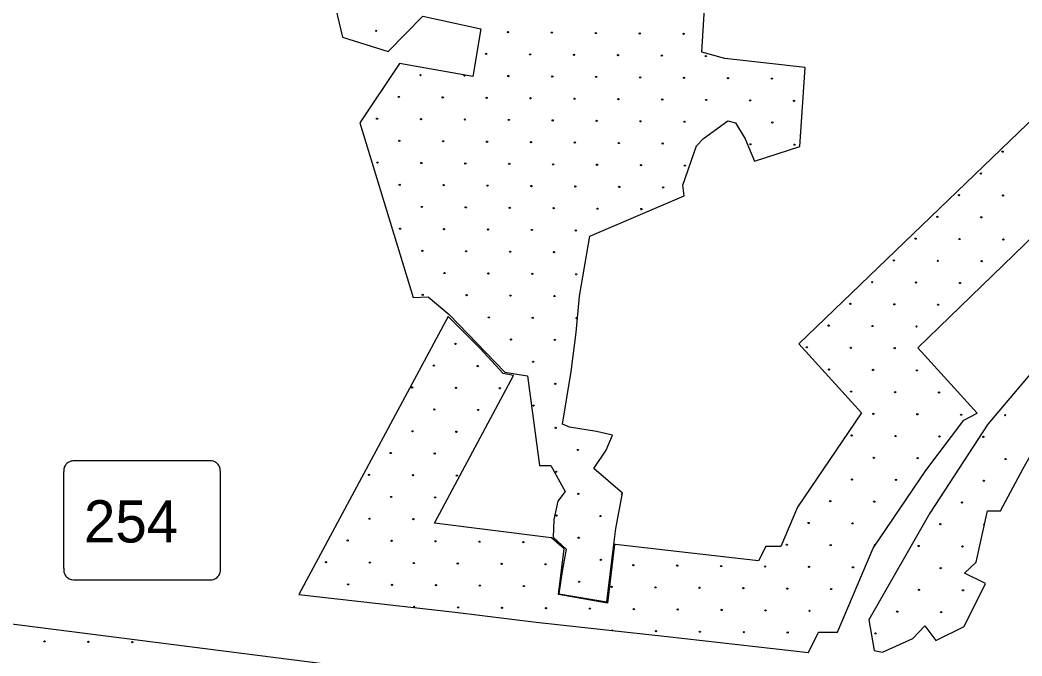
# Model space of a CAD drawing. Extents: x 1612280 to 1883141, y 560852 to 780851.
# Drawn here: x 1728435 to 1737209, y 621659 to 627229 of the extents above; entities that cross this region are included whole.
import ezdxf

# ---------------------------------------------------------------- set-up
doc = ezdxf.new("R2010")
doc.units = 0
for name, color, linetype in [('DESIGN - EROSION CONTROL - Devices', 7, 'Continuous'), ('DESIGN - ROW - Slope Lines', 7, 'Continuous'), ('DESIGN - SCRATCH - User 1', 7, 'Continuous')]:
    doc.layers.add(name, color=color, linetype=linetype)

msp = doc.modelspace()

# ---------------------------------------------------------------- linework, layer by layer
at = {"layer": 'DESIGN - EROSION CONTROL - Devices'}
for centre in [(1731554.3, 627133.4), (1731554.3, 627133.4), (1732707.9, 627122.2), (1732707.9, 627122.2), (1733092.5, 627118.5), (1733092.5, 627118.5), (1733477, 627114.8), (1733477, 627114.8), (1733861.6, 627111), (1733861.6, 627111), (1734246.1, 627107.3), (1734246.1, 627107.3), (1732517.5, 626931.8), (1732517.5, 626931.8), (1732902.1, 626928.1), (1732902.1, 626928.1), (1733286.6, 626924.4), (1733286.6, 626924.4), (1733671.2, 626920.6), (1733671.2, 626920.6), (1734055.7, 626916.9), (1734055.7, 626916.9), (1734440.3, 626913.2), (1734440.3, 626913.2), (1731942.6, 626745.1), (1731942.6, 626745.1), (1732327.1, 626741.4), (1732327.1, 626741.4), (1732711.7, 626737.7), (1732711.7, 626737.7), (1733096.2, 626733.9), (1733096.2, 626733.9), (1733480.8, 626730.2), (1733480.8, 626730.2), (1733865.3, 626726.5), (1733865.3, 626726.5), (1734249.9, 626722.7), (1734249.9, 626722.7), (1734634.4, 626719), (1734634.4, 626719), (1735019, 626715.3), (1735019, 626715.3), (1731752.1, 626554.7), (1731752.1, 626554.7), (1732136.7, 626551), (1732136.7, 626551), (1732521.2, 626547.3), (1732521.2, 626547.3), (1732905.8, 626543.5), (1732905.8, 626543.5), (1733290.4, 626539.8), (1733290.4, 626539.8), (1733674.9, 626536.1), (1733674.9, 626536.1), (1734059.5, 626532.3), (1734059.5, 626532.3), (1734444, 626528.6), (1734444, 626528.6), (1734828.6, 626524.9), (1734828.6, 626524.9), (1735213.1, 626521.1), (1735213.1, 626521.1), (1731561.7, 626364.3), (1731561.7, 626364.3), (1731946.3, 626360.6), (1731946.3, 626360.6), (1732330.8, 626356.9), (1732330.8, 626356.9), (1732715.4, 626353.1), (1732715.4, 626353.1), (1733099.9, 626349.4), (1733099.9, 626349.4), (1733484.5, 626345.7), (1733484.5, 626345.7), (1733869, 626341.9), (1733869, 626341.9), (1734253.6, 626338.2), (1734253.6, 626338.2), (1735022.7, 626330.7), (1735022.7, 626330.7), (1731755.9, 626170.2), (1731755.9, 626170.2), (1732140.4, 626166.4), (1732140.4, 626166.4), (1732525, 626162.7), (1732525, 626162.7), (1732909.5, 626159), (1732909.5, 626159), (1733294.1, 626155.2), (1733294.1, 626155.2), (1733678.6, 626151.5), (1733678.6, 626151.5), (1734063.2, 626147.8), (1734063.2, 626147.8), (1734832.3, 626140.3), (1734832.3, 626140.3), (1735216.9, 626136.6), (1735216.9, 626136.6), (1737039.2, 626075.8), (1737039.2, 626075.8), (1731565.5, 625979.8), (1731565.5, 625979.8), (1731950, 625976), (1731950, 625976), (1732334.6, 625972.3), (1732334.6, 625972.3), (1732719.1, 625968.6), (1732719.1, 625968.6), (1733103.7, 625964.8), (1733103.7, 625964.8), (1733488.2, 625961.1), (1733488.2, 625961.1), (1733872.8, 625957.4), (1733872.8, 625957.4), (1734257.3, 625953.6), (1734257.3, 625953.6), (1736848.7, 625885.4), (1736848.7, 625885.4), (1731759.6, 625785.6), (1731759.6, 625785.6), (1732144.2, 625781.9), (1732144.2, 625781.9), (1732528.7, 625778.2), (1732528.7, 625778.2), (1732913.3, 625774.4), (1732913.3, 625774.4), (1733297.8, 625770.7), (1733297.8, 625770.7), (1733682.4, 625767), (1733682.4, 625767), (1734066.9, 625763.2), (1734066.9, 625763.2), (1736658.3, 625695), (1736658.3, 625695), (1737042.9, 625691.2), (1737042.9, 625691.2), (1731953.8, 625591.5), (1731953.8, 625591.5), (1732338.3, 625587.8), (1732338.3, 625587.8), (1732722.9, 625584), (1732722.9, 625584), (1733107.4, 625580.3), (1733107.4, 625580.3), (1733492, 625576.5), (1733492, 625576.5), (1733876.5, 625572.8), (1733876.5, 625572.8), (1736467.9, 625504.5), (1736467.9, 625504.5), (1736852.5, 625500.8), (1736852.5, 625500.8), (1731763.3, 625401.1), (1731763.3, 625401.1), (1732147.9, 625397.3), (1732147.9, 625397.3), (1732532.4, 625393.6), (1732532.4, 625393.6), (1732917, 625389.9), (1732917, 625389.9), (1733301.6, 625386.1), (1733301.6, 625386.1), (1736277.5, 625314.1), (1736277.5, 625314.1), (1736662.1, 625310.4), (1736662.1, 625310.4), (1737046.6, 625306.7), (1737046.6, 625306.7), (1731957.5, 625206.9), (1731957.5, 625206.9), (1732342, 625203.2), (1732342, 625203.2), (1732726.6, 625199.5), (1732726.6, 625199.5), (1733111.1, 625195.7), (1733111.1, 625195.7), (1736087.1, 625123.7), (1736087.1, 625123.7), (1736471.7, 625120), (1736471.7, 625120), (1736856.2, 625116.3), (1736856.2, 625116.3), (1732151.6, 625012.8), (1732151.6, 625012.8), (1732536.2, 625009.1), (1732536.2, 625009.1), (1732920.7, 625005.3), (1732920.7, 625005.3), (1733305.3, 625001.6), (1733305.3, 625001.6), (1735896.7, 624933.3), (1735896.7, 624933.3), (1736281.2, 624929.6), (1736281.2, 624929.6), (1736665.8, 624925.9), (1736665.8, 624925.9), (1731961.2, 624822.4), (1731961.2, 624822.4), (1732345.8, 624818.6), (1732345.8, 624818.6), (1732730.3, 624814.9), (1732730.3, 624814.9), (1733114.9, 624811.2), (1733114.9, 624811.2), (1735706.3, 624742.9), (1735706.3, 624742.9), (1736090.8, 624739.2), (1736090.8, 624739.2), (1736475.4, 624735.4), (1736475.4, 624735.4), (1732539.9, 624624.5), (1732539.9, 624624.5), (1732924.5, 624620.8), (1732924.5, 624620.8), (1733309, 624617), (1733309, 624617), (1735515.9, 624552.5), (1735515.9, 624552.5), (1735900.4, 624548.8), (1735900.4, 624548.8), (1736285, 624545), (1736285, 624545), (1732734.1, 624430.4), (1732734.1, 624430.4), (1733118.6, 624426.6), (1733118.6, 624426.6), (1732249, 624392), (1732249, 624392), (1735325.5, 624362.1), (1735325.5, 624362.1), (1735710, 624358.4), (1735710, 624358.4), (1736094.6, 624354.6), (1736094.6, 624354.6), (1732058.6, 624201.5), (1732058.6, 624201.5), (1732443.2, 624197.8), (1732443.2, 624197.8), (1732928.2, 624236.2), (1732928.2, 624236.2), (1735519.6, 624167.9), (1735519.6, 624167.9), (1735904.2, 624164.2), (1735904.2, 624164.2), (1736288.7, 624160.5), (1736288.7, 624160.5), (1731868.2, 624011.1), (1731868.2, 624011.1), (1732252.8, 624007.4), (1732252.8, 624007.4), (1732637.3, 624003.7), (1732637.3, 624003.7), (1733122.3, 624042.1), (1733122.3, 624042.1), (1735713.8, 623973.8), (1735713.8, 623973.8), (1736098.3, 623970.1), (1736098.3, 623970.1), (1736482.9, 623966.3), (1736482.9, 623966.3), (1732062.4, 623817), (1732062.4, 623817), (1732446.9, 623813.3), (1732446.9, 623813.3), (1732931.9, 623851.7), (1732931.9, 623851.7), (1735907.9, 623779.7), (1735907.9, 623779.7), (1736292.4, 623775.9), (1736292.4, 623775.9), (1736677, 623772.2), (1736677, 623772.2), (1737061.6, 623768.5), (1737061.6, 623768.5), (1733126.1, 623657.5), (1733126.1, 623657.5), (1731872, 623626.6), (1731872, 623626.6), (1732256.5, 623622.9), (1732256.5, 623622.9), (1735717.5, 623589.3), (1735717.5, 623589.3), (1736102, 623585.5), (1736102, 623585.5), (1736486.6, 623581.8), (1736486.6, 623581.8), (1736871.1, 623578.1), (1736871.1, 623578.1), (1733320.2, 623463.4), (1733320.2, 623463.4), (1731681.5, 623436.2), (1731681.5, 623436.2), (1732066.1, 623432.4), (1732066.1, 623432.4), (1735911.6, 623395.1), (1735911.6, 623395.1), (1736296.2, 623391.4), (1736296.2, 623391.4), (1737065.3, 623383.9), (1737065.3, 623383.9), (1731491.1, 623245.8), (1731491.1, 623245.8), (1731875.7, 623242), (1731875.7, 623242), (1732260.2, 623238.3), (1732260.2, 623238.3), (1733129.8, 623273), (1733129.8, 623273), (1735721.2, 623204.7), (1735721.2, 623204.7), (1736105.8, 623201), (1736105.8, 623201), (1736874.9, 623193.5), (1736874.9, 623193.5), (1731685.3, 623051.6), (1731685.3, 623051.6), (1732069.8, 623047.9), (1732069.8, 623047.9), (1733324, 623078.8), (1733324, 623078.8), (1735530.8, 623014.3), (1735530.8, 623014.3), (1735915.4, 623010.6), (1735915.4, 623010.6), (1736684.5, 623003.1), (1736684.5, 623003.1), (1731494.9, 622861.2), (1731494.9, 622861.2), (1731879.4, 622857.5), (1731879.4, 622857.5), (1733133.5, 622888.4), (1733133.5, 622888.4), (1733518.1, 622884.7), (1733518.1, 622884.7), (1735340.4, 622823.9), (1735340.4, 622823.9), (1735725, 622820.1), (1735725, 622820.1), (1736494.1, 622812.7), (1736494.1, 622812.7), (1731304.5, 622670.8), (1731304.5, 622670.8), (1731689, 622667.1), (1731689, 622667.1), (1733327.7, 622694.3), (1733327.7, 622694.3), (1732073.6, 622663.3), (1732073.6, 622663.3), (1732458.1, 622659.6), (1732458.1, 622659.6), (1732842.7, 622655.9), (1732842.7, 622655.9), (1735150, 622633.5), (1735150, 622633.5), (1735534.5, 622629.7), (1735534.5, 622629.7), (1736303.6, 622622.3), (1736303.6, 622622.3), (1736688.2, 622618.5), (1736688.2, 622618.5), (1733521.8, 622500.1), (1733521.8, 622500.1), (1731114.1, 622480.4), (1731114.1, 622480.4), (1731498.6, 622476.7), (1731498.6, 622476.7), (1731883.2, 622472.9), (1731883.2, 622472.9), (1732267.7, 622469.2), (1732267.7, 622469.2), (1732652.3, 622465.5), (1732652.3, 622465.5), (1733036.8, 622461.7), (1733036.8, 622461.7), (1733805.9, 622454.3), (1733805.9, 622454.3), (1734190.5, 622450.5), (1734190.5, 622450.5), (1734575, 622446.8), (1734575, 622446.8), (1734959.6, 622443.1), (1734959.6, 622443.1), (1735344.1, 622439.3), (1735344.1, 622439.3), (1735728.7, 622435.6), (1735728.7, 622435.6), (1736497.8, 622428.1), (1736497.8, 622428.1), (1731308.2, 622286.3), (1731308.2, 622286.3), (1731692.7, 622282.5), (1731692.7, 622282.5), (1732077.3, 622278.8), (1732077.3, 622278.8), (1732461.9, 622275.1), (1732461.9, 622275.1), (1732846.4, 622271.3), (1732846.4, 622271.3), (1733331.4, 622309.7), (1733331.4, 622309.7), (1733615.5, 622263.9), (1733615.5, 622263.9), (1734000.1, 622260.1), (1734000.1, 622260.1), (1734384.6, 622256.4), (1734384.6, 622256.4), (1734769.2, 622252.6), (1734769.2, 622252.6), (1735153.7, 622248.9), (1735153.7, 622248.9), (1735538.3, 622245.2), (1735538.3, 622245.2), (1736307.4, 622237.7), (1736307.4, 622237.7), (1736691.9, 622234), (1736691.9, 622234), (1732271.4, 622084.6), (1732271.4, 622084.6), (1732656, 622080.9), (1732656, 622080.9), (1733040.5, 622077.2), (1733040.5, 622077.2), (1733425.1, 622073.4), (1733425.1, 622073.4), (1733809.7, 622069.7), (1733809.7, 622069.7), (1734194.2, 622066), (1734194.2, 622066), (1734578.8, 622062.2), (1734578.8, 622062.2), (1734963.3, 622058.5), (1734963.3, 622058.5), (1735347.9, 622054.8), (1735347.9, 622054.8), (1736117, 622047.3), (1736117, 622047.3), (1736501.5, 622043.6), (1736501.5, 622043.6), (1734003.8, 621875.6), (1734003.8, 621875.6), (1728648.9, 621787.1), (1728648.9, 621787.1), (1734388.4, 621871.8), (1734388.4, 621871.8), (1734772.9, 621868.1), (1734772.9, 621868.1), (1735157.5, 621864.4), (1735157.5, 621864.4), (1735926.6, 621856.9), (1735926.6, 621856.9), (1729033.4, 621783.4), (1729033.4, 621783.4), (1729418, 621779.7), (1729418, 621779.7)]:
    msp.add_circle(centre, 5.28, dxfattribs=at)
for centre, start, end in [((1733708.5, 623075.1), 75.50073, 263.45626), ((1736878.6, 622808.9), 58.23746, 276.59138), ((1735919.1, 622626), 32.37169, 259.39047), ((1730923.6, 622290), 287.00107, 16.61261), ((1731886.9, 622088.4), 271.24521, 255.91452), ((1733619.2, 621879.3), 40.66872, 126.38298)]:
    msp.add_arc(centre, 5.28, start, end, dxfattribs=at)
at = {"layer": 'DESIGN - ROW - Slope Lines'}
msp.add_line((1728817.1, 623266.8), (1728817.1, 622435), dxfattribs=at)
msp.add_line((1728817.1, 623266.8), (1728817.1, 622435), dxfattribs=at)
for points in [[(1730190, 623256.3), (1730189.9, 623264.1), (1730189.7, 623272.2), (1730188.7, 623286.8), (1730187.3, 623297.2), (1730185.5, 623308), (1730183.5, 623314), (1730180.3, 623320.6), (1730175.9, 623328.1), (1730170.5, 623335.5), (1730165.8, 623340.9), (1730159.9, 623346.5), (1730155.2, 623350.3), (1730148.8, 623354.8), (1730143.8, 623357.8), (1730135.5, 623361.8), (1730129.3, 623363.9), (1730122.2, 623365.3), (1730112.9, 623366.7), (1730104.8, 623367.5), (1730096.1, 623368.1), (1730083.8, 623368.2), (1730074.3, 623367.5), (1728917.1, 623368.2), (1728907.7, 623368.2), (1728897.4, 623367.5), (1728888.3, 623366.4), (1728879.2, 623364.7), (1728874.9, 623363.4), (1728867.7, 623360.3), (1728861.2, 623356.9), (1728856, 623353.7), (1728847.1, 623346.9), (1728841, 623341.1), (1728835.9, 623335.2), (1728831.9, 623329.9), (1728826.2, 623320.3), (1728822.8, 623312.9), (1728820.9, 623307.8), (1728820.2, 623304), (1728819.7, 623300.7), (1728818.8, 623293.4), (1728817.7, 623284.1), (1728817.3, 623276.2), (1728817.2, 623269.5), (1728817.1, 623251.6)], [(1730190, 623256.3), (1730189.9, 623264.1), (1730189.7, 623272.2), (1730188.7, 623286.8), (1730187.3, 623297.2), (1730185.5, 623308), (1730183.5, 623314), (1730180.3, 623320.6), (1730175.9, 623328.1), (1730170.5, 623335.5), (1730165.8, 623340.9), (1730159.9, 623346.5), (1730155.2, 623350.3), (1730148.8, 623354.8), (1730143.8, 623357.8), (1730135.5, 623361.8), (1730129.3, 623363.9), (1730122.2, 623365.3), (1730112.9, 623366.7), (1730104.8, 623367.5), (1730096.1, 623368.1), (1730083.8, 623368.2), (1730074.3, 623367.5), (1728917.1, 623368.2), (1728907.7, 623368.2), (1728897.4, 623367.5), (1728888.3, 623366.4), (1728879.2, 623364.7), (1728874.9, 623363.4), (1728867.7, 623360.3), (1728861.2, 623356.9), (1728856, 623353.7), (1728847.1, 623346.9), (1728841, 623341.1), (1728835.9, 623335.2), (1728831.9, 623329.9), (1728826.2, 623320.3), (1728822.8, 623312.9), (1728820.9, 623307.8), (1728820.2, 623304), (1728819.7, 623300.7), (1728818.8, 623293.4), (1728817.7, 623284.1), (1728817.3, 623276.2), (1728817.2, 623269.5), (1728817.1, 623251.6)], [(1730080.1, 622325.7), (1730100.8, 622326), (1730117.8, 622326.2), (1730128, 622328.7), (1730140.3, 622333.5), (1730151.5, 622339.9), (1730160.4, 622346.8), (1730168.5, 622354.8), (1730174.7, 622362.7), (1730180.7, 622372.5), (1730184.3, 622380.2), (1730186.9, 622387.3), (1730188.5, 622394.8), (1730189.2, 622403.1), (1730189.6, 622413.1), (1730190, 622436.4), (1730190, 623256.3)], [(1730080.1, 622325.7), (1730100.8, 622326), (1730117.8, 622326.2), (1730128, 622328.7), (1730140.3, 622333.5), (1730151.5, 622339.9), (1730160.4, 622346.8), (1730168.5, 622354.8), (1730174.7, 622362.7), (1730180.7, 622372.5), (1730184.3, 622380.2), (1730186.9, 622387.3), (1730188.5, 622394.8), (1730189.2, 622403.1), (1730189.6, 622413.1), (1730190, 622436.4), (1730190, 623256.3)], [(1728817.1, 622435), (1728817.3, 622426), (1728817.8, 622415.9), (1728818.6, 622406.4), (1728819.7, 622397.2), (1728821.1, 622388), (1728823.9, 622380.3), (1728827.3, 622373.1), (1728831.8, 622365.6), (1728837.2, 622358.3), (1728842.8, 622352.1), (1728850, 622345.5), (1728857, 622340.3), (1728865, 622335.6), (1728873.6, 622331.6), (1728882.5, 622328.5), (1728889.8, 622327.6), (1728904.7, 622326.4), (1728923.5, 622325.7), (1730080.1, 622325.7)], [(1728817.1, 622435), (1728817.3, 622426), (1728817.8, 622415.9), (1728818.6, 622406.4), (1728819.7, 622397.2), (1728821.1, 622388), (1728823.9, 622380.3), (1728827.3, 622373.1), (1728831.8, 622365.6), (1728837.2, 622358.3), (1728842.8, 622352.1), (1728850, 622345.5), (1728857, 622340.3), (1728865, 622335.6), (1728873.6, 622331.6), (1728882.5, 622328.5), (1728889.8, 622327.6), (1728904.7, 622326.4), (1728923.5, 622325.7), (1730080.1, 622325.7)]]:
    msp.add_lwpolyline(points, dxfattribs=at)
at = {"layer": 'DESIGN - SCRATCH - User 1'}
for points in [[(1731087.9, 627805.3), (1731258.1, 627080), (1731659, 626953.7), (1731961, 627261.4), (1732471.7, 627151.5), (1732400.3, 626733.9), (1731757.8, 626849.3)], [(1731087.9, 627805.3), (1731258.1, 627080), (1731659, 626953.7), (1731961, 627261.4), (1732471.7, 627151.5), (1732400.3, 626733.9), (1731757.8, 626849.3)], [(1734406, 626948.1), (1734436.8, 627476.1), (1734487.4, 627715.9)], [(1734406, 626948.1), (1734436.8, 627476.1), (1734487.4, 627715.9)], [(1737021.6, 622928.8), (1737218.5, 623299.9), (1737499.4, 623796.7), (1737882.4, 624199.2), (1738236.5, 624499.7), (1738713.8, 624934.9), (1738971.7, 625181.4), (1739106.4, 625458.7), (1739191.1, 625782.2), (1739241.2, 626132.7), (1739268.1, 626648.9), (1739325.1, 627161)], [(1737021.6, 622928.8), (1737218.5, 623299.9), (1737499.4, 623796.7), (1737882.4, 624199.2), (1738236.5, 624499.7), (1738713.8, 624934.9), (1738971.7, 625181.4), (1739106.4, 625458.7), (1739191.1, 625782.2), (1739241.2, 626132.7), (1739268.1, 626648.9), (1739325.1, 627161)], [(1738254.2, 626975), (1737949.5, 626985.3), (1735255.6, 624393.5), (1735803.4, 623788.5)], [(1738254.2, 626975), (1737949.5, 626985.3), (1735255.6, 624393.5), (1735803.4, 623788.5)], [(1735311.7, 626811.7), (1734608.3, 626890.9), (1734406, 626948.1)], [(1735311.7, 626811.7), (1734608.3, 626890.9), (1734406, 626948.1)], [(1731757.8, 626849.3), (1731411.9, 626327.3)], [(1731757.8, 626849.3), (1731411.9, 626327.3)], [(1735263.4, 626121), (1735311.7, 626811.7)], [(1735263.4, 626121), (1735311.7, 626811.7)], [(1731411.9, 626327.3), (1731878.6, 624799.7), (1732010.4, 624805.2), (1732193, 624650)], [(1731411.9, 626327.3), (1731878.6, 624799.7), (1732010.4, 624805.2), (1732193, 624650)], [(1734252.1, 625689.9), (1734238.9, 625782.2), (1734357.7, 626125.4), (1734419.2, 626191.4), (1734634.7, 626345.4)], [(1734252.1, 625689.9), (1734238.9, 625782.2), (1734357.7, 626125.4), (1734419.2, 626191.4), (1734634.7, 626345.4)], [(1734634.7, 626345.4), (1734700.6, 626327.8), (1734784.1, 626187), (1734867.7, 625993.4)], [(1734634.7, 626345.4), (1734700.6, 626327.8), (1734784.1, 626187), (1734867.7, 625993.4)], [(1734867.7, 625993.4), (1735263.4, 626121)], [(1734867.7, 625993.4), (1735263.4, 626121)], [(1736818.1, 623785.2), (1736298.5, 624359.1), (1738169.2, 626169.3), (1738230.8, 626123.1), (1738723.4, 625660.9), (1738477.1, 625268.1), (1737818.9, 624690.3)], [(1736818.1, 623785.2), (1736298.5, 624359.1), (1738169.2, 626169.3), (1738230.8, 626123.1), (1738723.4, 625660.9), (1738477.1, 625268.1), (1737818.9, 624690.3)], [(1733423.7, 625335.3), (1734252.1, 625689.9)], [(1733423.7, 625335.3), (1734252.1, 625689.9)], [(1733246.3, 623661.6), (1733186, 623689), (1733260, 624149.6), (1733303.8, 624492.2), (1733334, 624810.2), (1733423.7, 625335.3)], [(1733246.3, 623661.6), (1733186, 623689), (1733260, 624149.6), (1733303.8, 624492.2), (1733334, 624810.2), (1733423.7, 625335.3)], [(1737818.9, 624690.3), (1737472.5, 624355.2), (1736910.5, 623688.9), (1736402.4, 622910.9), (1735867.4, 621974.9), (1735915.4, 621707.4)], [(1737818.9, 624690.3), (1737472.5, 624355.2), (1736910.5, 623688.9), (1736402.4, 622910.9), (1735867.4, 621974.9), (1735915.4, 621707.4)], [(1732183.3, 624632.1), (1730877.9, 622196.6)], [(1732183.3, 624632.1), (1730877.9, 622196.6)], [(1732757.8, 624116.3), (1732666.4, 624132.7), (1732463.7, 624352.2), (1732183.3, 624632.1)], [(1732757.8, 624116.3), (1732666.4, 624132.7), (1732463.7, 624352.2), (1732183.3, 624632.1)], [(1732193, 624650), (1732681.9, 624144.1), (1732879.2, 624113.9), (1732984.7, 623325.8)], [(1732193, 624650), (1732681.9, 624144.1), (1732879.2, 624113.9), (1732984.7, 623325.8)], [(1732063.5, 622821.1), (1732757.8, 624116.3)], [(1732063.5, 622821.1), (1732757.8, 624116.3)], [(1735803.4, 623788.5), (1735243.9, 622962.8), (1735097.4, 622617.1), (1734965, 622617.1), (1734903.2, 622493.5)], [(1735803.4, 623788.5), (1735243.9, 622962.8), (1735097.4, 622617.1), (1734965, 622617.1), (1734903.2, 622493.5)], [(1735340.1, 621689.9), (1735428.6, 621867.1), (1735594.1, 621867.1), (1735905.9, 622602.7), (1736367.8, 623284.5), (1736698.8, 623723.6), (1736818.1, 623785.2)], [(1735340.1, 621689.9), (1735428.6, 621867.1), (1735594.1, 621867.1), (1735905.9, 622602.7), (1736367.8, 623284.5), (1736698.8, 623723.6), (1736818.1, 623785.2)], [(1733624.3, 623593.1), (1733481.9, 623626), (1733246.3, 623661.6)], [(1733624.3, 623593.1), (1733481.9, 623626), (1733246.3, 623661.6)], [(1733573.7, 622133.3), (1733631.2, 622613.1), (1733653.1, 622774.8), (1733710.6, 623084.6), (1733458.6, 623301.1), (1733568.2, 623460.1), (1733624.3, 623593.1)], [(1733573.7, 622133.3), (1733631.2, 622613.1), (1733653.1, 622774.8), (1733710.6, 623084.6), (1733458.6, 623301.1), (1733568.2, 623460.1), (1733624.3, 623593.1)], [(1732984.7, 623325.8), (1733083.3, 623325.8), (1733209.3, 623098.3), (1733143.6, 623016.1), (1733110.7, 622854.3), (1733102.5, 622700.8), (1733217.5, 622593.9), (1733181.5, 622402.5), (1733154.5, 622201.9)], [(1732984.7, 623325.8), (1733083.3, 623325.8), (1733209.3, 623098.3), (1733143.6, 623016.1), (1733110.7, 622854.3), (1733102.5, 622700.8), (1733217.5, 622593.9), (1733181.5, 622402.5), (1733154.5, 622201.9)], [(1736890.8, 622294.9), (1736706.9, 622384.9), (1736807, 622480.3), (1736907.2, 622928.8), (1737021.6, 622928.8)], [(1736890.8, 622294.9), (1736706.9, 622384.9), (1736807, 622480.3), (1736907.2, 622928.8), (1737021.6, 622928.8)], [(1734903.2, 622493.5), (1734185.1, 622573.8), (1733650.8, 622634.5), (1733641.3, 622633.8), (1733578.2, 622120.5), (1733150.7, 622197.6), (1733199.7, 622595.9), (1733089, 622692.7), (1733039.7, 622700), (1732063.5, 622821.1)], [(1734903.2, 622493.5), (1734185.1, 622573.8), (1733650.8, 622634.5), (1733641.3, 622633.8), (1733578.2, 622120.5), (1733150.7, 622197.6), (1733199.7, 622595.9), (1733089, 622692.7), (1733039.7, 622700), (1732063.5, 622821.1)], [(1735915.4, 621707.4), (1735986.9, 621693), (1736253.9, 621812.3), (1736358.8, 621922.1), (1736454.2, 621793.2), (1736702.1, 621917.3), (1736890.8, 622294.9)], [(1735915.4, 621707.4), (1735986.9, 621693), (1736253.9, 621812.3), (1736358.8, 621922.1), (1736454.2, 621793.2), (1736702.1, 621917.3), (1736890.8, 622294.9)], [(1727212, 622147.4), (1727832, 622007.1), (1731407.1, 621551.1), (1732026.4, 621504.3), (1734693.7, 621170.6)], [(1727212, 622147.4), (1727832, 622007.1), (1731407.1, 621551.1), (1732026.4, 621504.3), (1734693.7, 621170.6)], [(1730877.9, 622196.6), (1732245.2, 622042.8), (1732953.5, 621954.9), (1733568.5, 621889), (1734101.1, 621828.5), (1735340.1, 621689.9)], [(1730877.9, 622196.6), (1732245.2, 622042.8), (1732953.5, 621954.9), (1733568.5, 621889), (1734101.1, 621828.5), (1735340.1, 621689.9)], [(1733154.5, 622201.9), (1733573.7, 622133.3)], [(1733154.5, 622201.9), (1733573.7, 622133.3)]]:
    msp.add_lwpolyline(points, dxfattribs=at)

# ---------------------------------------------------------------- texts
at = {"layer": 'DESIGN - ROW - Slope Lines'}
msp.add_text('254', height=369.61, rotation=0.00108, dxfattribs=at).set_placement((1728995.1, 622653))
msp.add_text('254', height=369.61, rotation=0.00108, dxfattribs=at).set_placement((1728995.1, 622653))

doc.saveas('drawing.dxf')
